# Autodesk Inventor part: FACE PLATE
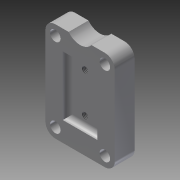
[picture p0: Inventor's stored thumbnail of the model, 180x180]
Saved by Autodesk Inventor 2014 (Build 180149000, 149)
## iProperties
Shininess: 64.0
Length Units: 11272
Angle Units: 11279
Time Units: 11290
Mass Units: 11286
Length Display Precision: 3
Angle Display Precision: 2
Compacted: True
Part Number: FACE PLATE
Document SubType Name: Modeling
Created: 2003-11
Designer: Autodesk, Inc.
Manufacturer: Standard
Standards Organization: Custom
Mass: 239.386 g
Surface Area: 93.2455 cm^2
Volume: 30.4562 cm^3
Density: 7.86 g/cm^3
Material: Steel, Mild
Appearance: Steel
Density: 0.0
Volumn: 0.0
Area: 0.0
PropertySet Name: Model Information
Control State: 0
Master: False
Checked Out: False
Author: Autodesk, Inc.
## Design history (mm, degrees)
sketch "Sketch1"
  geometry: L1 (0, 0)-(44.45, 0); L2 (44.45, 0)-(44.45, 63.5); L3 (44.45, 63.5)-(0, 63.5); L4 (0, 63.5)-(0, 0)
  constraints: 8 end point, 2 parallel, 1 horizontal, 1 perpendicular
  dimensions: "d0" = 44.45 distance between parallel lines of L2 L4; "d1" = 63.5 distance of L1.end L2.end
extrude "Extrusion1" new body sketch "Sketch1" distance "d2" = 12.7; taper "d3" = 0 deg
sketch "Sketch2"
  geometry: L1 (0, 0)-(0, 63.5) reference; L2 (44.45, 0)-(0, 0) reference; L3 (44.45, 63.5)-(44.45, 0) reference; L4 (0, 63.5)-(44.45, 63.5) reference; L5 (0, 31.75)-(44.45, 31.75); 4 further points
  constraints: 2 end point, 2 midpoint, 2 symmetric about line
  dimensions: "d4" = 6.35 distance from line of point (6.35, 57.15) L4; "d5" = 6.35 distance from line of L4 point (38.1, 57.15); "d6" = 6.35 distance from line of L1 point (6.35, 57.15); "d7" = 6.35 distance from line of L3 point (38.1, 57.15)
hole "Hole1" sketch "Sketch2" at (6.35, 57.15), (38.1, 57.15), (6.35, 6.35), (38.1, 6.35) diameter "d8" = 6.731; stored, may be unused: countersink angle "d12" = 82 deg, drill point angle "d14" = 118 deg; dims "d9" = 12.7, "d10" = 9.525, "d11" = 6.35, "d13" = 19.05
fillet "Fillet1" dims "d15" = 6.35
sketch "Sketch3"
  geometry: L1 (11.125, 50.8)-(33.35, 50.8); L2 (33.35, 50.8)-(33.35, 12.7); L3 (33.35, 12.7)-(11.125, 12.7); L4 (11.125, 12.7)-(11.125, 50.8); L5 (44.45, 57.15)-(44.45, 6.35) reference; L6 (38.1, 0)-(6.35, 0) reference
  constraints: 8 end point, 2 parallel, 1 horizontal, 1 perpendicular
  dimensions: "d16" = 11.0998 distance between parallel lines of L5 L2; "d17" = 22.225 distance between parallel lines of L2 L4; "d18" = 12.7 distance between parallel lines of L6 L3; "d19" = 38.1 distance between parallel lines of L3 L1
extrude "Extrusion2" cut sketch "Sketch3" distance "d20" = 3.175; taper "d21" = 0 deg
sketch "Sketch4"
  geometry: L1 (14.3, 15.875)-(14.3, 47.625) reference; L2 (30.175, 47.625)-(30.175, 15.875) reference; L3 (14.3, 47.625)-(30.175, 47.625) reference; L4 (14.3, 31.75)-(30.175, 31.75); L5 (30.175, 15.875)-(14.3, 15.875) reference; C1 r 3.365 at (6.35, 57.15) reference; 1 further point
  constraints: 2 end point, 2 midpoint
  dimensions: "d23" = 15.875 horizontal distance of C1.centre point (22.225, 44.45); "d24" = 12.7 vertical distance of point (22.225, 44.45) C1.centre
hole "Hole2" sketch "Sketch4" at (22.225, 44.45) diameter "d25" = 3.9624; stored, may be unused: countersink angle "d29" = 82 deg, drill point angle "d31" = 118 deg; dims "d26" = 12.7, "d27" = 9.525, "d28" = 6.35, "d30" = 19.05
workplane "Work Plane1"
mirror "Mirror1"
sketch "Sketch5"
  geometry: C1 r 9.274 at (-22.225, 69.17)
  constraints: 1 centre point
extrude "Extrusion3" cut sketch "Sketch5" stored distance "d33" = 25.4; taper "d34" = 0 deg
fillet "Fillet3" dims "d39" = 3.175
body "Solid1"
node "Projected Loop1"
other parameters: "d32" = -31.75, "d35" = 0, "d36" = 0, "d37" = 0, "d38" = 0
